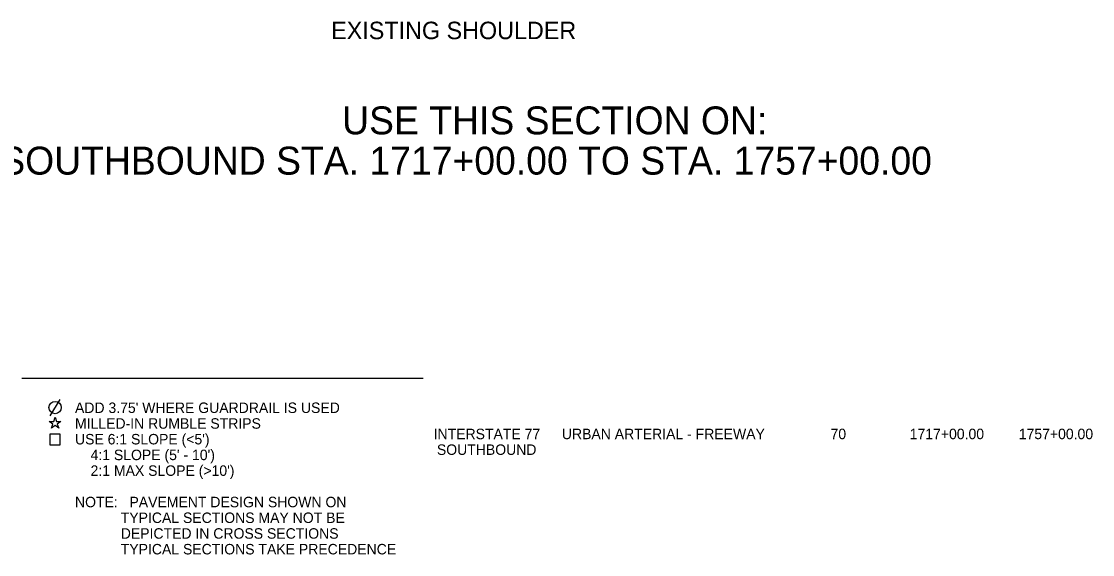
# Model space of a CAD drawing. Extents: x 2003207 to 2014043, y 843846 to 860154.
# Drawn here: x 2013655.7 to 2013717.1, y 844447.2 to 844477.7 of the extents above; entities that cross this region are included whole.
import ezdxf

# ---------------------------------------------------------------- set-up
doc = ezdxf.new("R2010")
doc.units = 0
for name, color, linetype in [('RD_EX_Road_txCode', 7, 'Continuous'), ('RD_SHT_Bndy', 7, 'Continuous'), ('RD_SHT_TX', 7, 'Continuous'), ('RD_TX_TypSect', 7, 'Continuous')]:
    doc.layers.add(name, color=color, linetype=linetype)

msp = doc.modelspace()

# ---------------------------------------------------------------- linework, layer by layer
at = {"layer": 'RD_EX_Road_txCode'}
msp.add_line((2013657.384, 844455.107), (2013657.95, 844456.05), dxfattribs=at)
for points in [[(2013657.335, 844454.786), (2013657.589, 844454.786), (2013657.667, 844455.028), (2013657.746, 844454.786), (2013658, 844454.786), (2013657.795, 844454.637), (2013657.873, 844454.395), (2013657.667, 844454.544), (2013657.462, 844454.395), (2013657.54, 844454.637)], [(2013657.367, 844453.452), (2013657.967, 844453.452), (2013657.967, 844454.052), (2013657.367, 844454.052)]]:
    msp.add_lwpolyline(points, close=True, dxfattribs=at)
msp.add_circle((2013657.667, 844455.578), 0.35, dxfattribs=at)
at = {"layer": 'RD_SHT_Bndy'}
msp.add_line((2013678.755, 844457.242), (2013655.755, 844457.242), dxfattribs=at)

# ---------------------------------------------------------------- texts
at = {"layer": 'RD_EX_Road_txCode'}
for s, height, p in [('USE THIS SECTION ON:', 1.6, (2013674.116, 844471.227)), ('I-77 SOUTHBOUND STA. 1717+00.00 TO STA. 1757+00.00', 1.6, (2013650.242, 844468.922)), ("ADD 3.75' WHERE GUARDRAIL IS USED", 0.6, (2013658.808, 844455.268)), ('MILLED-IN RUMBLE STRIPS', 0.6, (2013658.808, 844454.368)), ("USE 6:1 SLOPE (<5')", 0.6, (2013658.808, 844453.468)), ("    4:1 SLOPE (5' - 10')", 0.6, (2013658.808, 844452.568)), ("    2:1 MAX SLOPE (>10')", 0.6, (2013658.808, 844451.668)), ('NOTE:   PAVEMENT DESIGN SHOWN ON', 0.6, (2013658.808, 844449.868)), (' TYPICAL SECTIONS MAY NOT BE ', 0.6, (2013661.208, 844448.968)), (' DEPICTED IN CROSS SECTIONS', 0.6, (2013661.208, 844448.068)), (' TYPICAL SECTIONS TAKE PRECEDENCE', 0.6, (2013661.208, 844447.168))]:
    msp.add_text(s, height=height, dxfattribs=at).set_placement(p)
at = {"layer": 'RD_SHT_TX'}
for s, p in [('INTERSTATE 77', (2013679.362, 844453.768)), ('URBAN ARTERIAL - FREEWAY', (2013686.711, 844453.768)), ('70', (2013702.109, 844453.768)), ('1717+00.00', (2013706.647, 844453.768)), ('1757+00.00', (2013712.897, 844453.768)), ('SOUTHBOUND', (2013679.549, 844452.868))]:
    msp.add_text(s, height=0.6, dxfattribs=at).set_placement(p)
at = {"layer": 'RD_TX_TypSect'}
msp.add_text('EXISTING SHOULDER', height=1, dxfattribs=at).set_placement((2013673.49, 844476.68))

doc.saveas('drawing.dxf')
